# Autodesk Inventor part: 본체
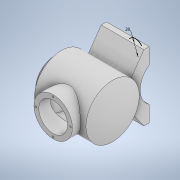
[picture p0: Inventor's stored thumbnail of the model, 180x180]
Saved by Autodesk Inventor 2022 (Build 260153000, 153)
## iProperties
Created: 2023-04
Part Number: 본체
Material: 일반
Document SubType Name: Modeling
Designer: Admin
Density: 1 g/cm^3
Appearance: 기본값
Author: Admin
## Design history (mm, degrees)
sketch "스케치1" dims "d7" = 226
  geometry: L1 (-211.2, 0)-(105.2, 0) reference; L2 (0, -158.2)-(0, 158.2) reference; L3 (-60, 0)-(-48, 0); L4 (-48, 0)-(-48, 36); L5 (-48, 36)-(-60, 36); L6 (-60, 36)-(-60, 0); L7 (-48, 0)-(60, 0); L8 (60, 0)-(60, 50); L9 (48.336, 50)-(-48, 50); L10 (-48, 50)-(-48, 0); L11 (-34.38, 0)-(50.398, 0); 5 further points
  constraints: 18 end point, 4 parallel, 4 point on line, 2 horizontal, 2 perpendicular, 1 vertical, 4 other
  dimensions: "d0" = 72 diameter of L5 L1; "d1" = 100 diameter of L9 L1; "d3" = 120 distance between parallel lines of L8 L6; "d4" = 108 distance between parallel lines of L8 L4
revolve "회전1" sketch "스케치1" stored, may be unused: angle "d5" = 360 deg
sketch "스케치3" dims "d12" = 226
  geometry: L1 (-60, 0)-(-41, 0); L2 (-41, 0)-(-41, 27); L3 (-41, 27)-(-60, 27); L4 (-60, 27)-(-60, 0); L5 (-41, 0)-(53, 0); L6 (53, 0)-(53, 43); L7 (53, 43)-(-41, 43); L8 (-41, 43)-(-41, 0); L9 (0, -158.2)-(0, 158.2) reference; L10 (-211.2, 0)-(105.2, 0) reference; L11 (48.336, -50)-(48.336, 50) reference; L12 (-60, -36)-(-60, 36) reference; C1 r 106 at (-53, 0); 4 further points
  constraints: 16 end point, 4 parallel, 2 collinear, 2 horizontal, 2 perpendicular, 1 centre point, 1 midpoint, 1 tangent, 3 other
  dimensions: "d8" = 19 distance between parallel lines of L2 L4; "d9" = 54 diameter of L3 L10; "d10" = 86 diameter of L7 L10; "d17" = 7 dimension on C1
revolve "회전2" sketch "스케치3" stored, may be unused: angle "d18" = 90 deg
node "작업 평면1"
sketch "스케치4"
  geometry: L1 (-79.6, 0)-(57.6, 0) reference; L2 (0, -50.4)-(0, 50.4) reference; L3 (-60, -36)-(-60, 36) reference; C1 r 36 at (2, 0); 1 further point
  constraints: 1 centre point, 1 point on line
  dimensions: "d20" = 62 distance from line of C1.centre L3; "d21" = 72 diameter of C1
extrude "돌출1" join sketch "스케치4" stored distance "d22" = 10; taper "d23" = 0 deg
sketch "스케치5"
  geometry: C1 r 36 at (0, 0) reference; C2 r 27 at (0, 0); 1 further point
  constraints: 1 centre point, 1 coincident
  dimensions: "d24" = 54 diameter of C2
extrude "돌출2" cut sketch "스케치5" stored distance "d25" = 10; taper "d26" = 0 deg
sketch "스케치6"
  geometry: L1 (0, -70)-(0, 70) reference; L2 (-70, 0)-(70, 0) reference; A1 r 32.5 centre (0, 0) between (32.5, 0) and (0, -32.5); 3 further points
  constraints: 4 point on circle, 4 point on line, 1 centre point, 1 coincident
  dimensions: "d27" = 65 diameter of A1
hole "구멍1" sketch "스케치6" at (32.5, 0), (0, -32.5), (-32.5, 0), (0, 32.5) diameter "d28" = 3.242; stored, may be unused: countersink angle "d32" = 90 deg, drill point angle "d34" = 118 deg; dims "d29" = 8, "d30" = 4, "d31" = 2, "d33" = 10
sketch "스케치7" dims "d35" = 65
  geometry: L1 (-86, 0)-(82, 0) reference; C1 r 27 at (0, 0) reference; 6 further points
  constraints: 1 coincident, 1 horizontal alignment, 1 point on line, 7 other
  dimensions: "d38" = 360 deg dimension on C1.centre point (-32.5, 0) (derived)
hole "구멍2" sketch "스케치7" at (-32.5, 0), (0, -32.5), (32.5, 0), (0, 32.5) diameter "d40" = 3.242; stored, may be unused: countersink angle "d44" = 90 deg, drill point angle "d46" = 118 deg; dims "d41" = 8, "d42" = 4, "d43" = 2, "d45" = 10
node "작업 평면2"
sketch "스케치8"
  geometry: L1 (0, -70)-(0, 70) reference; L2 (-77, 64.015)-(-77, -74.706); L3 (-77, -62)-(-67, -62); L4 (-67, -62)-(-40.123, -23.615); L5 (-105.4, 0)-(93.4, 0) reference; L6 (-46.557, 0)-(-77, 0); L7 (-77, -62)-(-77, 0); C1 r 43 at (0, 0) reference; A1 r 46.557 centre (0, 0) between (-40.123, -23.615) and (-46.557, 0); 1 further point
  constraints: 10 end point, 4 point on line, 2 point on circle, 1 centre point, 1 coincident, 1 collinear, 1 horizontal, 1 vertical
  dimensions: "d48" = 77 distance between parallel lines of L1 L2; "d49" = 10 distance of L3.start L3.end; "d50" = 55 deg angle of L3 L4; "d51" = 62 distance between parallel lines of L5 L3; "d55" = 93.11303 diameter of A1
extrude "돌출3" join sketch "스케치8" distance "d56" = 80; taper "d57" = 0 deg
sketch "스케치9"
  geometry: L1 (-60, -38.5)-(-108.227, -38.5); L2 (-60, 38.5)-(-108.227, 38.5); L3 (-77, 62)-(-67, 62) reference; L4 (-77, -62)-(-67, -62) reference; L5 (-177.4, 0)-(105.4, 0) reference; L6 (-60, 38.5)-(-60, -38.5); L7 (-77, 62)-(-77, -62) reference; C1 r 38.5 at (-98.5, 0); 3 further points
  constraints: 6 end point, 2 horizontal, 2 tangent, 1 centre point, 1 point on line, 1 vertical, 1 other
  dimensions: "d58" = 77 distance between parallel lines of L2 L1; "d59" = 17 distance between parallel lines of L7 L6
extrude "돌출4" cut sketch "스케치9" stored distance "d61" = 80; taper "d62" = 0 deg
sketch "스케치11"
  geometry: L1 (80, 124)-(0, 124) reference; L2 (80, 0)-(0, 0) reference; L3 (124, 62)-(-44, 62) reference; L4 (107.736, 116)-(-32.889, 116); L5 (107.736, 8)-(-41.889, 8); L6 (60, 143.936)-(60, -34.577); L7 (80, 30.063)-(80, 0) reference; L8 (20, 139.994)-(20, -34.577); 5 further points
  constraints: 8 end point, 8 point on line, 2 horizontal, 2 vertical
  dimensions: "d63" = 108 distance between parallel lines of L4 L5; "d64" = 8 distance between parallel lines of L2 L5; "d65" = 20 distance between parallel lines of L7 L6; "d66" = 40 distance between parallel lines of L6 L8
hole "구멍3" sketch "스케치11" at (60, 8), (20, 8), (60, 116), (20, 116) diameter "d67" = 9; stored, may be unused: countersink angle "d71" = 90 deg, drill point angle "d73" = 0 deg; dims "d68" = 8, "d69" = 4, "d70" = 2, "d72" = 6
sketch "스케치12"
  geometry: C1 r 4.5 at (0, 0) reference; C2 r 14 at (0, 0); 1 further point
  constraints: 1 centre point, 1 coincident
  dimensions: "d74" = 28 diameter of C2
node "솔리드1"
mirror "미러1"
feature "A9D066F2-1C7D-4E18-AEED-F7BC21143FA4" dims "d67" = 9, "d68" = 8, "d69" = 4, "d70" = 2, "d71" = 90 deg, "d72" = 6, "d73" = 0
other parameters: "d19" = 65
